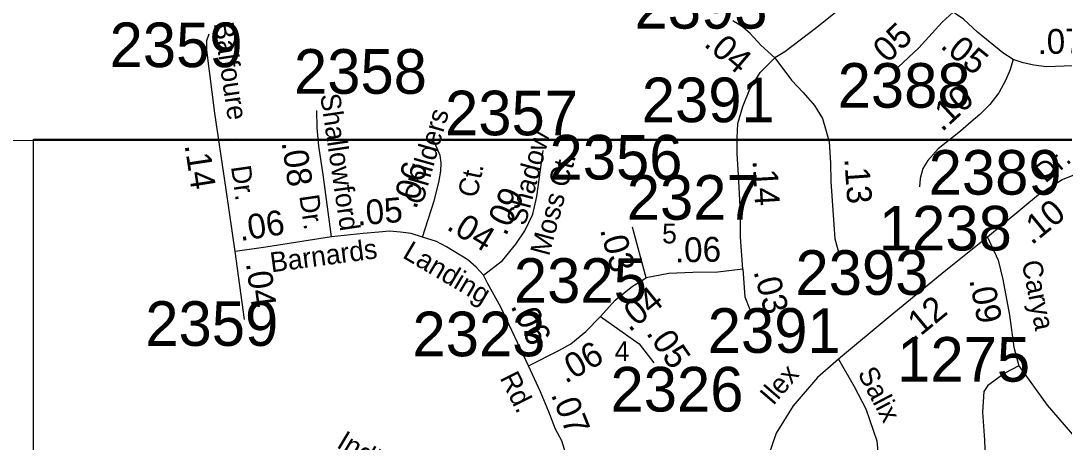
# Model space of a CAD drawing. Extents: x 1945482 to 2853149, y 66427 to 1015778.
# Drawn here: x 2325374 to 2328820, y 147688 to 149081 of the extents above; entities that cross this region are included whole.
import ezdxf

# ---------------------------------------------------------------- set-up
doc = ezdxf.new("R2010")
doc.units = 0
for name, color, linetype in [('Old_Level_11', 7, 'Continuous'), ('Old_Level_17', 7, 'Continuous'), ('Old_Level_25', 7, 'Continuous'), ('Old_Level_32', 7, 'Continuous'), ('Old_Level_35', 7, 'Continuous'), ('Old_Level_63', 7, 'Continuous'), ('Old_Level_8', 7, 'Continuous')]:
    doc.layers.add(name, color=color, linetype=linetype)

msp = doc.modelspace()

# ---------------------------------------------------------------- linework, layer by layer
at = {"layer": 'Old_Level_25'}
msp.add_line((2316886.9, 148684.9), (2347995, 148689.9), dxfattribs=at)
at = {"layer": 'Old_Level_32'}
for points in [[(2328300.9, 149271.3), (2328189.8, 149201.3), (2328103.8, 149140.4), (2328003.4, 149059.6), (2327897.6, 148978.9), (2327864.5, 148959.2)], [(2327864.5, 148959.2), (2327818.8, 149000.5), (2327782.9, 149039.9), (2327757.8, 149061.4), (2327725.6, 149081.2)], [(2328271.7, 148927.9), (2328340, 148992.7), (2328417, 149076.8), (2328453.3, 149109.9)], [(2328652.3, 148953.8), (2328618.2, 148975.3), (2328534, 149043.5), (2328487.4, 149086.5), (2328453.3, 149109.9)], [(2326082.5, 148318.9), (2326052.9, 148523.2), (2326014.5, 148775.9), (2325988.1, 148984.2), (2325988.1, 149016.5), (2325995.8, 149038.4)], [(2327758.7, 148259.7), (2327751.6, 148365.5), (2327751.6, 148446.2), (2327744.4, 148571.8), (2327740.8, 148641.7), (2327740.8, 148693.8), (2327742.6, 148742.2), (2327758.7, 148797.8), (2327782, 148855.2), (2327816.1, 148910.8), (2327864.5, 148959.2)], [(2327864.5, 148959.2), (2327919.2, 148885.7), (2327958.6, 148844.4), (2327996.2, 148801.4), (2328022.2, 148758.3), (2328032.1, 148724.2), (2328044.6, 148681.2), (2328048.2, 148611.3), (2328050, 148550.3), (2328063.4, 148360.1), (2328076, 148313.5)], [(2328652.3, 148953.8), (2328641, 148917.4), (2328627, 148884.1), (2328604.3, 148843.8), (2328574.5, 148805.3), (2328541.3, 148772), (2328513.3, 148747.5), (2328477.5, 148716.2), (2328404, 148657.9), (2328370.2, 148619.2), (2328353.9, 148593.6), (2328344.7, 148559.8), (2328343, 148532)], [(2329009.4, 148886.2), (2328940.9, 148912.6), (2328897.8, 148924.2), (2328867.8, 148929.9), (2328846.4, 148932.3), (2328819.9, 148931.8), (2328762.3, 148929.6), (2328719.8, 148935.3), (2328685.5, 148942.1), (2328652.3, 148953.8)], [(2326399.8, 148367.3), (2326372.3, 148573.8), (2326358.1, 148667.1), (2326352.6, 148727.6), (2326351.5, 148784.7)], [(2326700.6, 148366.2), (2326739, 148485.9), (2326754.4, 148546.3), (2326761, 148584.8), (2326762.1, 148612.2), (2326758.8, 148636.4), (2326742.3, 148674.8), (2326732.4, 148690.2)], [(2326901.9, 148239.8), (2326964.8, 148288.8), (2327009, 148342.4), (2327039.3, 148386.7), (2327064.9, 148442.6), (2327078.9, 148500.8), (2327099.9, 148652.3)], [(2328988.1, 148582), (2328935.1, 148584.6), (2328859.8, 148574.1), (2328813.9, 148555.6), (2328735.7, 148506.3), (2328567.3, 148365.7)], [(2327439.7, 148231), (2327394.9, 148399.6)], [(2326399.8, 148367.3), (2326183.5, 148333.2), (2326082.5, 148318.9)], [(2326700.6, 148366.2), (2326663.3, 148378.2), (2326628.1, 148382.6), (2326591.9, 148385.9), (2326556.8, 148382.6), (2326505.2, 148378.2), (2326399.8, 148367.3)], [(2326901.9, 148239.8), (2326878.4, 148267.3), (2326850.7, 148291.1), (2326779.6, 148334.3), (2326746.7, 148351.9), (2326700.6, 148366.2)], [(2328567.3, 148365.7), (2328429.6, 148256.2), (2328245.5, 148104.8), (2328074.9, 147962.2)], [(2328567.3, 148365.7), (2328602.7, 148290.4), (2328617.8, 148225.9), (2328639.3, 148107.5), (2328654.3, 148002.1), (2328671, 147940.4)], [(2326112.8, 148093.9), (2326082.5, 148318.9)], [(2327758.7, 148259.7), (2327676.3, 148250.7), (2327593.8, 148248.9), (2327515, 148245.4), (2327439.7, 148231)], [(2327758.7, 148259.7), (2327765.9, 148168.2), (2327782, 148127)], [(2327051.4, 147940.1), (2326960.1, 148135), (2326915.9, 148214.2), (2326901.9, 148239.8)], [(2327289.1, 148103.7), (2327337.5, 148157.5), (2327394.9, 148204.1), (2327439.7, 148231)], [(2327051.4, 147940.1), (2327153.2, 147991.9), (2327190.4, 148012.9), (2327240.1, 148054.5), (2327289.1, 148103.7)], [(2327289.1, 148103.7), (2327416.2, 148012.9), (2327465, 147950.1)], [(2327187.8, 147588.6), (2327179.1, 147634.8), (2327161.3, 147692.7), (2327140.3, 147731.5), (2327117.7, 147788.1), (2327090.2, 147854.4), (2327051.4, 147940.1)], [(2328074.9, 147962.2), (2328005.4, 147901.4), (2327925.1, 147808), (2327868.6, 147717.8), (2327845.1, 147647.2), (2327842.8, 147596.9), (2327839.3, 147489.5), (2327846.4, 147316.8), (2327854.2, 147169.1), (2327876.7, 146956), (2327867.1, 146786.4), (2327870.4, 146695.9)], [(2328074.9, 147962.2), (2328126.7, 147872.1), (2328165.8, 147797.8), (2328201.7, 147692.9), (2328212, 147583.3), (2328219.2, 147221), (2328228.5, 147057.8), (2328232.6, 146881.2), (2328255, 146775.7)], [(2328671, 147940.4), (2328624.2, 147916.1), (2328568.3, 147875.2), (2328555.4, 147855.8), (2328551.1, 147787), (2328557.6, 147694.4), (2328563.9, 147519.3), (2328561.6, 147384.1), (2328604.6, 147216.8), (2328652.2, 147105.1), (2328692.9, 147052.3), (2328722.4, 147019.3)], [(2328671, 147940.4), (2328764, 147810.6), (2328903.9, 147648.7), (2329008.8, 147519), (2329060.3, 147437), (2329133.7, 147324.6)]]:
    msp.add_lwpolyline(points, dxfattribs=at)
at = {"layer": 'Old_Level_35'}
for p, q in [((2326086.8, 148692.3), (2326086.8, 148692.6)), ((2326410.7, 148692.3), (2326410.6, 148692.5)), ((2326790, 148692.2), (2326790, 148692.5))]:
    msp.add_line(p, q, dxfattribs=at)
at = {"layer": 'Old_Level_63'}
msp.add_lwpolyline([(2343900.4, 141886.2), (2325416.4, 141886.2), (2325416.4, 148689.8), (2346064.1, 148689.8)], dxfattribs=at)

# ---------------------------------------------------------------- texts
at = {"layer": 'Old_Level_11'}
for s, height, rotation, p in [('Balfoure', 65.62, 278.3865, (2326011.2, 149073.1)), ('Shallowford', 65.617, 278.4111, (2326362.7, 148836.5)), ('Childers', 65.62, 74.0657, (2326700.6, 148470.1)), ('Shadow', 65.62, 74.9426, (2327040.4, 148401)), ('Moss Ct.', 65.62, 74.9426, (2327118.7, 148300.9)), ('Dr.', 65.62, 39.8532, (2328758.5, 148542.8)), ('Dr.', 65.62, 278.0588, (2326068.1, 148599.1)), ('Ct.', 65.62, 78.241, (2326880.9, 148493.8)), ('Dr.', 65.62, 278.4111, (2326293.6, 148502.4)), ('Barnards', 65.62, 7.6007, (2326201.7, 148249.5)), ('Landing', 65.62, 329.4684, (2326631.5, 148300)), ('Carya', 65.62, 281.1814, (2328679.8, 148283.3)), ('Ilex', 65.62, 49.3138, (2327859, 147806.5)), ('Rd.', 65.62, 296.5587, (2326955, 147900.8)), ('Salix', 65.62, 297.6417, (2328136.8, 147916.2)), ('Indian', 65.62, 329.0159, (2326413.7, 147672.8))]:
    msp.add_text(s, height=height, rotation=rotation, dxfattribs=at).set_placement(p)
for s, p in [('5', (2327492.3, 148345.4)), ('4', (2327335.7, 147956.2))]:
    msp.add_text(s, height=65.6, dxfattribs=at).set_placement(p)
at = {"layer": 'Old_Level_17'}
for s, rotation, p in [('.05', 43.5104, (2328214.6, 148918)), ('.07', 1.17, (2328733.1, 148971.2)), ('.04', 319.3818, (2327627, 149000.8)), ('.05', 321.0265, (2328408.1, 148994.2)), ('.10', 42.9631, (2328417, 148712.1)), ('.08', 278.6901, (2326235, 148679.3)), ('.14', 278.6472, (2325914.9, 148670.2)), ('.06', 75.7279, (2326680.5, 148455.5)), ('.14', 273.2683, (2327791, 148619.6)), ('.13', 274.0446, (2328094, 148625.7)), ('.09', 65.3902, (2326976.1, 148366.9)), ('.05', 4.8676, (2326486.3, 148404.1)), ('.06', 8.9482, (2326099.4, 148352.9)), ('.10', 39.4332, (2328713.2, 148337.8)), ('.04', 328.6969, (2326776.6, 148393.8)), ('.03', 284.8846, (2327286.7, 148390.7)), ('.06', 1.2463, (2327535.4, 148282.2)), ('.04', 277.6505, (2326117.4, 148279.8)), ('.03', 284.8846, (2327793.6, 148252.6)), ('.09', 281.1814, (2328506.5, 148224.6)), ('.04', 39.1113, (2327384.4, 148049.7)), ('.12', 39.4332, (2328322.8, 148018.2)), ('.06', 295.0979, (2326990.6, 148138.4)), ('.05', 304.6742, (2327437.6, 148048.6)), ('.06', 29.4905, (2327173, 147880.3)), ('.07', 291.79, (2327124, 147845.4))]:
    msp.add_text(s, height=82.02, rotation=rotation, dxfattribs=at).set_placement(p)
at = {"layer": 'Old_Level_8'}
for s, p in [('2393', (2327401.4, 149055.7)), ('2359', (2325667.3, 148928.3)), ('2358', (2326276.3, 148840.3)), ('2388', (2328072.2, 148794.1)), ('2391', (2327425.2, 148746.2)), ('2357', (2326775.3, 148702.8)), ('2356', (2327120.5, 148556.6)), ('2389', (2328372.8, 148506.5)), ('2327', (2327375.6, 148423.7)), ('1238', (2328208.3, 148321.9)), ('2393', (2327932.8, 148175.2)), ('2325', (2327002.8, 148148.8)), ('2359', (2325785.2, 148006.4)), ('2323', (2326667.7, 147972)), ('2391', (2327643, 147983.4)), ('1275', (2328268.7, 147888.1)), ('2326', (2327321.9, 147789.3))]:
    msp.add_text(s, height=147.64, dxfattribs=at).set_placement(p)

doc.saveas('drawing.dxf')
